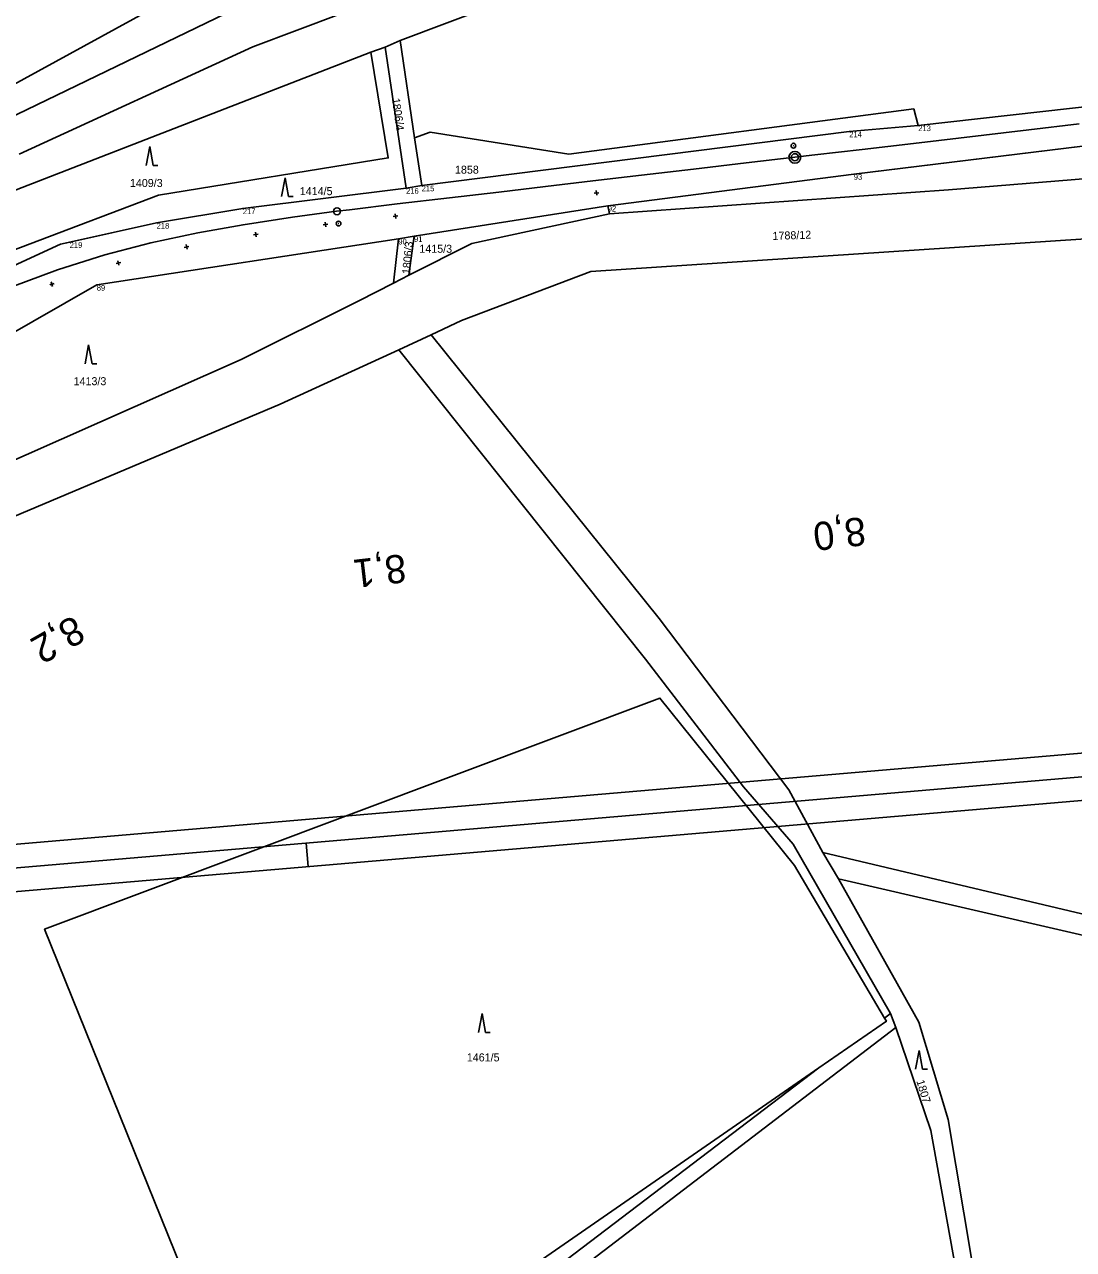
# Model space of a CAD drawing. Extents: x -779330 to -774454, y -1144748 to -1142831.
# Drawn here: x -778233.6 to -778010.9, y -1143916.7 to -1143656.5 of the extents above; entities that cross this region are included whole.
import ezdxf

# ---------------------------------------------------------------- set-up
doc = ezdxf.new("R2010")
doc.units = 0
for name, color, linetype in [('Hranice parcel', 7, 'Continuous'), ('Parcelní čísla', 7, 'Continuous'), ('PUPFL - do 50 m', 7, 'Continuous'), ('SŽDC', 7, 'Continuous'), ('Vnitřní kresba', 7, 'Continuous'), ('Vrstva 1', 7, 'Continuous'), ('Vrstva 53', 7, 'Continuous'), ('Vrstva 60', 7, 'Continuous'), ('Vrstva 7', 7, 'Continuous'), ('Značky kultur', 7, 'Continuous')]:
    doc.layers.add(name, color=color, linetype=linetype)

msp = doc.modelspace()

# ---------------------------------------------------------------- linework, layer by layer
at = {"layer": 'Hranice parcel'}
for p, q in [((-778153.87, -1143659.9), (-778157.08, -1143661.33)), ((-778153.87, -1143659.9), (-778150.86, -1143680.58)), ((-778157.08, -1143661.33), (-778160.14, -1143662.37)), ((-778152.63, -1143691.27), (-778157.08, -1143661.33)), ((-777958.1, -1143676.15), (-778057.57, -1143688.29)), ((-778149.31, -1143690.75), (-778150.86, -1143680.58)), ((-778057.57, -1143688.29), (-778109.8, -1143695.04)), ((-778152.63, -1143691.27), (-778149.31, -1143690.75)), ((-778109.8, -1143695.04), (-778150.93, -1143701.48)), ((-778109.8, -1143695.04), (-778109.45, -1143696.76)), ((-778150.93, -1143701.48), (-778154.26, -1143702.04)), ((-778150.93, -1143701.48), (-778152.04, -1143709.77)), ((-778154.26, -1143702.04), (-778218.29, -1143711.84)), ((-778155.29, -1143711.47), (-778154.26, -1143702.04)), ((-778152.04, -1143709.77), (-778155.29, -1143711.47)), ((-778154.14, -1143725.63), (-778147.27, -1143722.43)), ((-778064.15, -1143832.38), (-778060.8, -1143837.94)), ((-778051.04, -1143867.53), (-778049.75, -1143866.54)), ((-778048.61, -1143869.54), (-778049.75, -1143866.54)), ((-778212.5, -1143990.19), (-778064.97, -1143878.1))]:
    msp.add_line(p, q, dxfattribs=at)
for points in [[(-777790.37, -1143627.42), (-777855.1, -1143618.66), (-777921.25, -1143618.32), (-777922.61, -1143618.31), (-777931.96, -1143618.26), (-778063.42, -1143629.9), (-778133.34, -1143652.18), (-778153.87, -1143659.9)], [(-778278.76, -1143694.3), (-778273.37, -1143691.09), (-778270.08, -1143689.13), (-778253.97, -1143679.1), (-778194.13, -1143646.31), (-778184.18, -1143642.68)], [(-778043.88, -1143677.97), (-777959.48, -1143668.5), (-777917.42, -1143663.44), (-777916.16, -1143663.29), (-777860.31, -1143656.58)], [(-778160.14, -1143662.37), (-778266.47, -1143703.7), (-778272.9, -1143709.81)], [(-778262.39, -1143715.02), (-778259.76, -1143713.44), (-778205.17, -1143692.74), (-778156.42, -1143684.85), (-778160.14, -1143662.37)], [(-778150.86, -1143680.58), (-778147.52, -1143679.38), (-778118.06, -1143684.08), (-778044.82, -1143674.45), (-778043.88, -1143677.97)], [(-778043.88, -1143677.97), (-778058.53, -1143679.28), (-778149.31, -1143690.75)], [(-777815.03, -1143678.47), (-777841.31, -1143681.49), (-777896.76, -1143691.8), (-777921.73, -1143695.03), (-777972.88, -1143699.73), (-778113.43, -1143708.98), (-778140.87, -1143719.35), (-778147.27, -1143722.43)], [(-778109.45, -1143696.76), (-778037.43, -1143691.63), (-777961.06, -1143685.39), (-777922.91, -1143682.18), (-777915.24, -1143681.28)], [(-778258.15, -1143717.99), (-778226.02, -1143703.2), (-778205.58, -1143698.68), (-778187.29, -1143695.6), (-778152.63, -1143691.27)], [(-778152.04, -1143709.77), (-778138.69, -1143703.04), (-778109.45, -1143696.76)], [(-778313.21, -1143795.87), (-778309.09, -1143791.5), (-778294.43, -1143775.14), (-778283.89, -1143767.8), (-778255.89, -1143757.86), (-778187.65, -1143727.69), (-778162.69, -1143715.23), (-778155.29, -1143711.47)], [(-778218.29, -1143711.84), (-778252.34, -1143731.3), (-778297.62, -1143763.5)], [(-778147.27, -1143722.43), (-778098.92, -1143782.64), (-778071.39, -1143819.05), (-778064.15, -1143832.38)], [(-778154.14, -1143725.63), (-778179.34, -1143737.13), (-778262.61, -1143772.29), (-778285.69, -1143783.2), (-778298.53, -1143795.65), (-778343.69, -1143848.48), (-778375.32, -1143880.74), (-778394.75, -1143898.05), (-778401.03, -1143902.99), (-778411.09, -1143910.58), (-778464.29, -1143949.38), (-778492.24, -1143968.43), (-778546.37, -1143995.76), (-778568.54, -1144004.65), (-778592.3, -1144003.98), (-778622.87, -1144002.93), (-778634.83, -1144006.49), (-778697.09, -1144033.84)], [(-778049.75, -1143866.54), (-778070.41, -1143830.57), (-778080.96, -1143818.39), (-778101.8, -1143791.33), (-778154.14, -1143725.63)], [(-778064.97, -1143878.1), (-778184.19, -1143960.58), (-778229.36, -1143848.61), (-778098.73, -1143799.56), (-778070.15, -1143835.13), (-778051.04, -1143867.53)], [(-778064.15, -1143832.38), (-777897.94, -1143871.72), (-777864.55, -1143880.59)], [(-777863.49, -1143883.95), (-777884, -1143878.82), (-778060.8, -1143837.94)], [(-778060.8, -1143837.94), (-778043.76, -1143868.41), (-778037.53, -1143889.04), (-778029.28, -1143938.38), (-778025.36, -1143987.95), (-778008.42, -1144097.2)], [(-778051.04, -1143867.53), (-778050.65, -1143868.2), (-778064.97, -1143878.1)], [(-778048.61, -1143869.54), (-778198.33, -1143983.99), (-778209.77, -1143992.26)], [(-778011.94, -1144100.5), (-778030.06, -1143987.4), (-778033.63, -1143933.51), (-778041.2, -1143891.36), (-778048.61, -1143869.54)]]:
    msp.add_lwpolyline(points, dxfattribs=at)
at = {"layer": 'PUPFL - do 50 m'}
for p, q in [((-778152.04, -1143709.77), (-778155.29, -1143711.47)), ((-778154.14, -1143725.63), (-778147.27, -1143722.43))]:
    msp.add_line(p, q, dxfattribs=at)
for points in [[(-777915.24, -1143681.28), (-777917.11, -1143671.65), (-777958.1, -1143676.15), (-778057.57, -1143688.29), (-778109.8, -1143695.04), (-778109.45, -1143696.76), (-778037.43, -1143691.63), (-777961.06, -1143685.39), (-777922.91, -1143682.18)], [(-777921.73, -1143695.03), (-777972.88, -1143699.73), (-778113.43, -1143708.98), (-778140.87, -1143719.35), (-778147.27, -1143722.43), (-778098.92, -1143782.64), (-778071.39, -1143819.05), (-778064.15, -1143832.38), (-777897.94, -1143871.72), (-777864.55, -1143880.59), (-777823.97, -1143691.22), (-777815.03, -1143678.47), (-777841.31, -1143681.49), (-777896.76, -1143691.8)]]:
    msp.add_lwpolyline(points, close=True, dxfattribs=at)
for points in [[(-777961.06, -1143685.39), (-778037.43, -1143691.63), (-778109.45, -1143696.76)], [(-778147.27, -1143722.43), (-778140.87, -1143719.35), (-778113.43, -1143708.98), (-777972.88, -1143699.73), (-777921.73, -1143695.03)], [(-778109.45, -1143696.76), (-778138.69, -1143703.04), (-778152.04, -1143709.77)], [(-778155.29, -1143711.47), (-778162.69, -1143715.23), (-778187.65, -1143727.69), (-778255.89, -1143757.86), (-778283.89, -1143767.8), (-778294.43, -1143775.14), (-778309.09, -1143791.5), (-778313.21, -1143795.87)], [(-778697.09, -1144033.84), (-778634.83, -1144006.49), (-778622.87, -1144002.93), (-778592.3, -1144003.98), (-778568.54, -1144004.65), (-778546.37, -1143995.76), (-778492.24, -1143968.43), (-778464.29, -1143949.38), (-778411.09, -1143910.58), (-778401.03, -1143902.99), (-778394.75, -1143898.05), (-778375.32, -1143880.74), (-778343.69, -1143848.48), (-778298.53, -1143795.65), (-778285.69, -1143783.2), (-778262.61, -1143772.29), (-778179.34, -1143737.13), (-778154.14, -1143725.63)]]:
    msp.add_lwpolyline(points, dxfattribs=at)
at = {"layer": 'SŽDC'}
for points in [[(-777959.48, -1143668.5), (-778043.88, -1143677.97), (-778058.53, -1143679.28), (-778149.31, -1143690.75), (-778152.63, -1143691.27), (-778187.29, -1143695.6), (-778205.58, -1143698.68), (-778226.02, -1143703.2), (-778258.15, -1143717.99), (-778272.82, -1143725.14), (-778282.28, -1143733.16), (-778303.35, -1143750.75), (-778311.99, -1143760.43), (-778318.36, -1143767.45), (-778340.39, -1143793.1), (-778380.18, -1143839.73), (-778395.28, -1143859.46), (-778422.45, -1143890.8)], [(-778729.25, -1143967.31), (-778639.48, -1143961.79), (-778596.33, -1143959.85), (-778554.83, -1143958.91), (-778528.85, -1143955.36), (-778505.36, -1143949.37), (-778478.41, -1143938.21), (-778464.29, -1143932.05), (-778441.4, -1143918.51), (-778436.49, -1143914.8), (-778408.15, -1143894.88), (-778382.36, -1143870.73), (-778366.88, -1143851.34), (-778343.47, -1143820.07), (-778329.6, -1143802.5), (-778322.41, -1143793.6), (-778297.62, -1143763.5), (-778252.34, -1143731.3), (-778218.29, -1143711.84), (-778154.26, -1143702.04), (-778150.93, -1143701.48), (-778109.8, -1143695.04), (-778057.57, -1143688.29), (-777958.1, -1143676.15)]]:
    msp.add_lwpolyline(points, dxfattribs=at)
at = {"layer": 'Vnitřní kresba'}
for p, q in [((-778185.13, -1143661.25), (-778150.48, -1143648.2)), ((-778188.71, -1143653.12), (-778241.42, -1143678.62)), ((-778185.13, -1143661.25), (-778234.77, -1143684.06))]:
    msp.add_line(p, q, dxfattribs=at)
at = {"layer": 'Vrstva 1'}
msp.add_line((-778173.83, -1143830.37), (-778173.41, -1143835.34), dxfattribs=at)
for points in [[(-777571, -1143485.76), (-778617.18, -1143575.21), (-778591.88, -1143871.12), (-777545.7, -1143781.67)], [(-777551.11, -1143777.12), (-778587.32, -1143865.71), (-778611.77, -1143579.77), (-777575.56, -1143491.17)], [(-777580.11, -1143496.57), (-778407.09, -1143567.28), (-778383.5, -1143843.27), (-777556.51, -1143772.57)]]:
    msp.add_lwpolyline(points, close=True, dxfattribs=at)
msp.add_lwpolyline([(-778009.69, -1143677.64), (-778020.39, -1143678.89), (-778044.92, -1143681.77), (-778055.76, -1143683.04), (-778065.87, -1143684.22), (-778070.06, -1143684.71), (-778080.39, -1143685.93), (-778091.61, -1143687.25), (-778102.65, -1143688.55), (-778112.94, -1143689.76), (-778123.01, -1143690.94), (-778132.93, -1143692.1), (-778143.44, -1143693.33), (-778154.53, -1143694.64), (-778164.63, -1143695.85), (-778167.38, -1143696.2), (-778176.74, -1143697.44), (-778187.24, -1143699.04), (-778196.87, -1143700.77), (-778206.85, -1143702.9), (-778216.6, -1143705.44), (-778226.66, -1143708.61), (-778236.33, -1143712.24)], dxfattribs=at)
at = {"layer": 'Vrstva 53'}
for points in [[(-778224.04, -1143702.76), (-778205.58, -1143698.68), (-778187.29, -1143695.6), (-778152.63, -1143691.27), (-778149.31, -1143690.75), (-778058.53, -1143679.28), (-778043.88, -1143677.97), (-777959.48, -1143668.5), (-777917.42, -1143663.44), (-777916.16, -1143663.29), (-777860.31, -1143656.58), (-777817.61, -1143650.87), (-777782.23, -1143650.25), (-777777.65, -1143650.04), (-777771.99, -1143649.79), (-777747.07, -1143649.03), (-777716.22, -1143651.23), (-777687.78, -1143654.61), (-777659.91, -1143659.97), (-777643.37, -1143663.67), (-777619.92, -1143670.03), (-777600.4, -1143675.56)], [(-778224.04, -1143702.76), (-778205.58, -1143698.68), (-778187.29, -1143695.6), (-778152.63, -1143691.27), (-778149.31, -1143690.75), (-778058.53, -1143679.28), (-778043.88, -1143677.97), (-777959.48, -1143668.5), (-777917.42, -1143663.44), (-777916.16, -1143663.29), (-777860.31, -1143656.58), (-777817.61, -1143650.87), (-777782.23, -1143650.25), (-777777.65, -1143650.04), (-777771.99, -1143649.79), (-777747.07, -1143649.03), (-777716.22, -1143651.23), (-777687.78, -1143654.61), (-777659.91, -1143659.97), (-777643.37, -1143663.67), (-777619.92, -1143670.03), (-777600.4, -1143675.56)], [(-777550.6, -1143697.9), (-777622.38, -1143677.44), (-777645.06, -1143671.66), (-777661.41, -1143667.34), (-777716.9, -1143658.83), (-777747.1, -1143656.66), (-777769.78, -1143657.38), (-777774.83, -1143658.21), (-777780.87, -1143658.4), (-777816.72, -1143661.12), (-777859.44, -1143665.66), (-777917.11, -1143671.65), (-777958.1, -1143676.15), (-778057.57, -1143688.29), (-778109.8, -1143695.04), (-778150.93, -1143701.48), (-778154.26, -1143702.04), (-778218.29, -1143711.84)], [(-777550.6, -1143697.9), (-777622.38, -1143677.44), (-777645.06, -1143671.66), (-777661.41, -1143667.34), (-777716.9, -1143658.83), (-777747.1, -1143656.66), (-777769.78, -1143657.38), (-777774.83, -1143658.21), (-777780.87, -1143658.4), (-777816.72, -1143661.12), (-777859.44, -1143665.66), (-777917.11, -1143671.65), (-777958.1, -1143676.15), (-778057.57, -1143688.29), (-778109.8, -1143695.04), (-778150.93, -1143701.48), (-778154.26, -1143702.04), (-778218.29, -1143711.84)], [(-778395.28, -1143859.46), (-778380.18, -1143839.73), (-778340.39, -1143793.1), (-778318.36, -1143767.45), (-778311.99, -1143760.43), (-778303.35, -1143750.75), (-778282.28, -1143733.16), (-778272.82, -1143725.14), (-778258.15, -1143717.99), (-778226.02, -1143703.2)], [(-778395.28, -1143859.46), (-778380.18, -1143839.73), (-778340.39, -1143793.1), (-778318.36, -1143767.45), (-778311.99, -1143760.43), (-778303.35, -1143750.75), (-778282.28, -1143733.16), (-778272.82, -1143725.14), (-778258.15, -1143717.99), (-778226.02, -1143703.2)], [(-778224.04, -1143702.76), (-778226.02, -1143703.2)], [(-778224.04, -1143702.76), (-778226.02, -1143703.2)], [(-778218.29, -1143711.84), (-778252.34, -1143731.3), (-778297.62, -1143763.5), (-778322.41, -1143793.6), (-778329.6, -1143802.5), (-778343.47, -1143820.07), (-778366.88, -1143851.34), (-778382.36, -1143870.73)], [(-778218.29, -1143711.84), (-778252.34, -1143731.3), (-778297.62, -1143763.5), (-778322.41, -1143793.6), (-778329.6, -1143802.5), (-778343.47, -1143820.07), (-778366.88, -1143851.34), (-778382.36, -1143870.73)]]:
    msp.add_lwpolyline(points, dxfattribs=at)
at = {"layer": 'Vrstva 60'}
for p, q in [((-778043.88, -1143677.97), (-778043.88, -1143677.97)), ((-778058.53, -1143679.28), (-778058.53, -1143679.28)), ((-778057.57, -1143688.29), (-778057.57, -1143688.29)), ((-778152.63, -1143691.27), (-778152.63, -1143691.27)), ((-778149.31, -1143690.75), (-778149.31, -1143690.75)), ((-778187.29, -1143695.6), (-778187.29, -1143695.6)), ((-778109.8, -1143695.04), (-778109.8, -1143695.04)), ((-778205.58, -1143698.68), (-778205.58, -1143698.68)), ((-778150.93, -1143701.48), (-778150.93, -1143701.48)), ((-778224.04, -1143702.76), (-778224.04, -1143702.76)), ((-778154.26, -1143702.04), (-778154.26, -1143702.04)), ((-778218.29, -1143711.84), (-778218.29, -1143711.84))]:
    msp.add_line(p, q, dxfattribs=at)
at = {"layer": 'Vrstva 7'}
for p, q in [((-778070.32, -1143682.25), (-778070.42, -1143682.26)), ((-778111.69, -1143692.24), (-778112.69, -1143692.35)), ((-778112.13, -1143692.79), (-778112.25, -1143691.8)), ((-778169.23, -1143698.92), (-778170.23, -1143699.05)), ((-778169.67, -1143699.48), (-778169.79, -1143698.49)), ((-778166.91, -1143698.79), (-778167.01, -1143698.81)), ((-778154.36, -1143697.15), (-778155.35, -1143697.27)), ((-778154.79, -1143697.7), (-778154.91, -1143696.71)), ((-778184, -1143701.04), (-778184.99, -1143701.19)), ((-778184.42, -1143701.61), (-778184.57, -1143700.62)), ((-778198.73, -1143703.64), (-778199.71, -1143703.87)), ((-778199.11, -1143704.24), (-778199.34, -1143703.26)), ((-778213.22, -1143707.06), (-778214.2, -1143707.29)), ((-778213.6, -1143707.66), (-778213.83, -1143706.69)), ((-778227.34, -1143711.5), (-778228.29, -1143711.8)), ((-778227.67, -1143712.13), (-778227.97, -1143711.17))]:
    msp.add_line(p, q, dxfattribs=at)
for centre, radius in [((-778070.08, -1143684.72), 1.25), ((-778070.37, -1143682.26), 0.5), ((-778070.08, -1143684.72), 0.752), ((-778167.29, -1143696.19), 0.75), ((-778166.96, -1143698.8), 0.5)]:
    msp.add_circle(centre, radius, dxfattribs=at)
at = {"layer": 'Značky kultur'}
for p, q in [((-778207.05, -1143682.45), (-778207.8, -1143686.45)), ((-778206.3, -1143686.45), (-778207.05, -1143682.45)), ((-778206.3, -1143686.45), (-778205.3, -1143686.45)), ((-778178.33, -1143689.06), (-778179.08, -1143693.06)), ((-778177.58, -1143693.06), (-778178.33, -1143689.06)), ((-778177.58, -1143693.06), (-778176.58, -1143693.06)), ((-778220.02, -1143724.57), (-778220.77, -1143728.57)), ((-778219.27, -1143728.57), (-778220.02, -1143724.57)), ((-778219.27, -1143728.57), (-778218.27, -1143728.57)), ((-778136.5, -1143866.57), (-778137.25, -1143870.57)), ((-778135.75, -1143870.57), (-778136.5, -1143866.57)), ((-778135.75, -1143870.57), (-778134.75, -1143870.57)), ((-778043.7, -1143874.37), (-778044.45, -1143878.37)), ((-778042.95, -1143878.37), (-778043.7, -1143874.37)), ((-778042.95, -1143878.37), (-778041.95, -1143878.37))]:
    msp.add_line(p, q, dxfattribs=at)

# ---------------------------------------------------------------- texts
at = {"layer": 'Parcelní čísla'}
for s, rotation, p in [('1806/4', 278, (-778155.64, -1143672.27)), ('1788/12', 2, (-778074.79, -1143702.28)), ('1806/3', 85, (-778151.77, -1143709.6)), ('1807', 287, (-778044.3, -1143880.9))]:
    msp.add_text(s, height=1.7, rotation=rotation, dxfattribs=at).set_placement(p)
for s, p in [('1858', (-778142.24, -1143688.21)), ('1409/3', (-778211.26, -1143691.04)), ('1414/5', (-778175.19, -1143692.77)), ('1415/3', (-778149.81, -1143705)), ('1413/3', (-778223.22, -1143733.12)), ('1461/5', (-778139.73, -1143876.71))]:
    msp.add_text(s, height=1.7, dxfattribs=at).set_placement(p)
at = {"layer": 'Vrstva 60'}
for s, p in [('213', (-778043.88, -1143679.17)), ('214', (-778058.53, -1143680.48)), ('93', (-778057.57, -1143689.49)), ('216', (-778152.63, -1143692.47)), ('215', (-778149.31, -1143691.95)), ('217', (-778187.29, -1143696.8)), ('92', (-778109.8, -1143696.24)), ('218', (-778205.58, -1143699.88)), ('91', (-778150.93, -1143702.68)), ('219', (-778224.04, -1143703.96)), ('90', (-778154.26, -1143703.24)), ('89', (-778218.29, -1143713.04))]:
    msp.add_text(s, height=1.2, dxfattribs=at).set_placement(p)
at = {"layer": 'Vrstva 7'}
for s, rotation, p in [('8,0', 186.7318, (-778055.41, -1143761.06)), ('8,1', 186.6769, (-778153, -1143768.95)), ('8,2', 209.5392, (-778223.16, -1143781.81))]:
    msp.add_text(s, height=6, rotation=rotation, dxfattribs=at).set_placement(p)

doc.saveas('drawing.dxf')
